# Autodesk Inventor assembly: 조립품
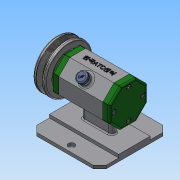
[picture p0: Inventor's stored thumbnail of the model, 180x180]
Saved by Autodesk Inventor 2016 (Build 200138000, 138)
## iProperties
Created: 2018-06
Part Number: 조립품
Document SubType Name: Weldment
Designer: MIRAE
Weld Material: Welded Aluminum-6061
Author: MIRAE
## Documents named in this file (16)
- C:\Users\MIRAE\Desktop\480607V1004\조립품.iam
- C:\Users\MIRAE\Desktop\480607V1004\V벨트풀리.ipt
- C:\Users\MIRAE\Desktop\480607V1004\고무캡.ipt
- C:\Users\MIRAE\Desktop\480607V1004\너트 M8.ipt
- 너트 M8.ipt
- C:\Users\MIRAE\Desktop\480607V1004\뒤커버.ipt
- C:\Users\MIRAE\Desktop\480607V1004\베어링 15x32x9.ipt
- C:\Users\MIRAE\Desktop\480607V1004\본체.ipt
- C:\Users\MIRAE\Desktop\480607V1004\볼트 M4x12.ipt
- C:\Users\MIRAE\Desktop\480607V1004\스프링와셔 8.ipt
- C:\Users\MIRAE\Desktop\480607V1004\앞커버.ipt
- C:\Users\MIRAE\Desktop\480607V1004\오일 실 15 25 7.ipt
- C:\Users\MIRAE\Desktop\480607V1004\와셔 8x17.ipt
- C:\Users\MIRAE\Desktop\480607V1004\축.ipt
- C:\Users\MIRAE\Desktop\480607V1004\키 3x3x12.ipt
- 키 3x3x12.ipt
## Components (2 placed, 2 different names)
1. V벨트풀리:1
2. 고무캡:1
